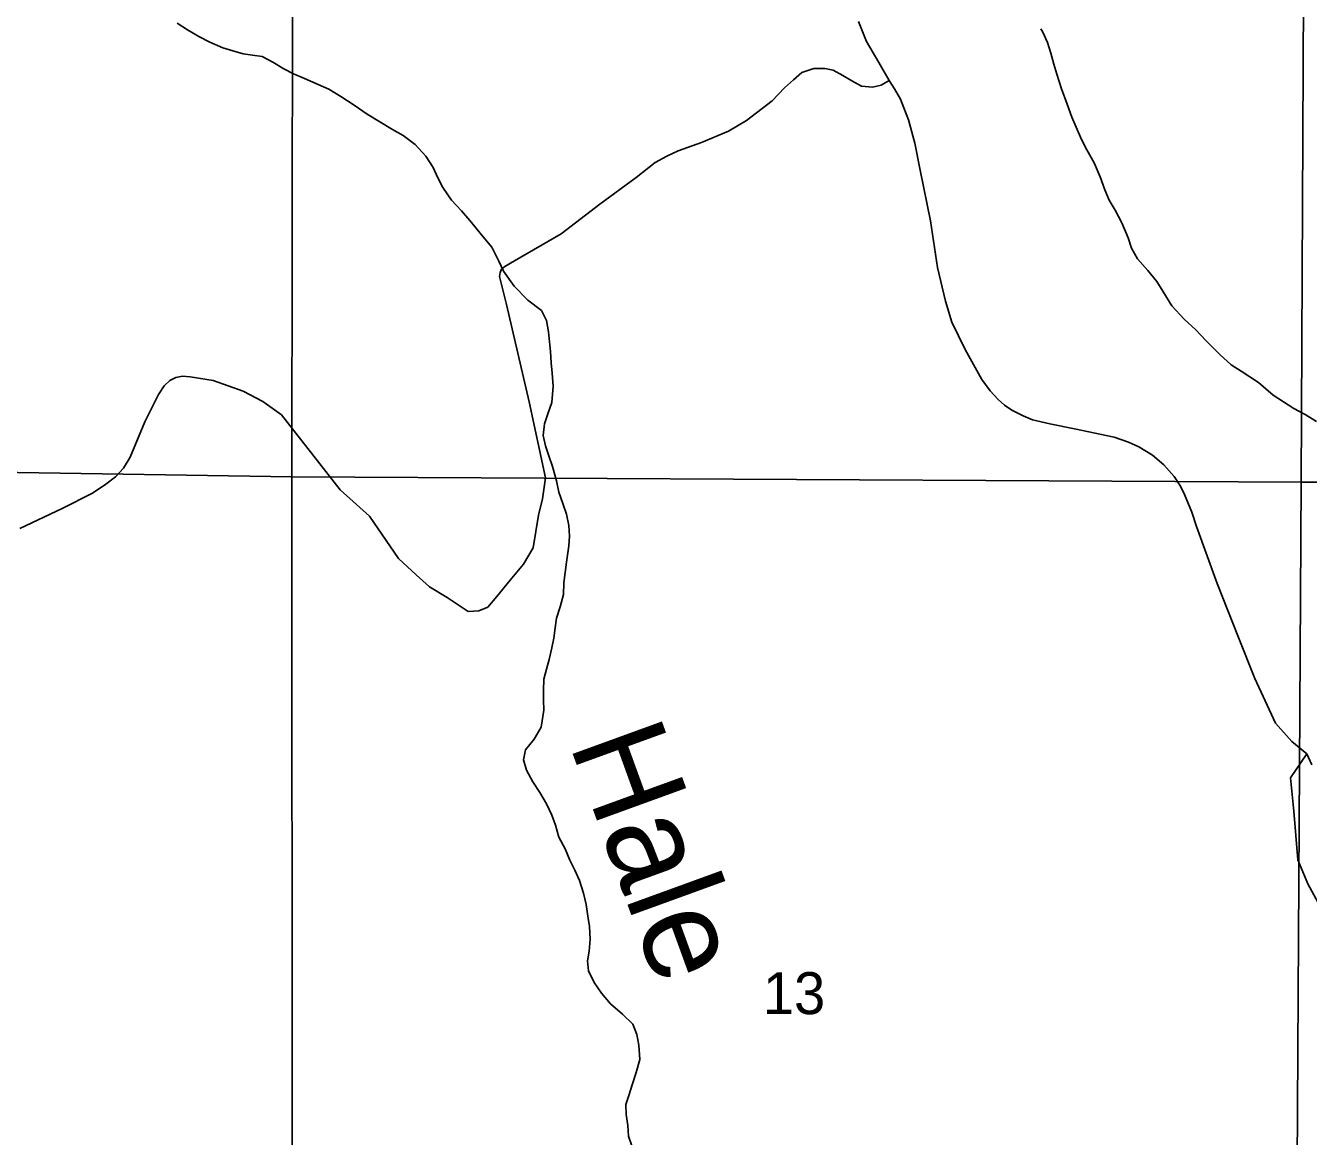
# Model space of a CAD drawing. Extents: x 0 to 34, y 0 to 22.
# Drawn here: x 3.273 to 4.552, y 19.493 to 20.6 of the extents above; entities that cross this region are included whole.
import ezdxf

# ---------------------------------------------------------------- set-up
doc = ezdxf.new("R2010")
doc.units = 0
for name, color, linetype in [('Default', 7, 'Continuous'), ('GM_X_Minor_River', 7, 'Continuous'), ('GM_X_Minor_River_Text', 7, 'Continuous'), ('GM_X_Section', 7, 'Continuous'), ('GM_X_Section_Text', 7, 'Continuous'), ('GM_X_State_Route', 7, 'Continuous'), ('GM_X_Township_Road', 7, 'Continuous')]:
    doc.layers.add(name, color=color, linetype=linetype)

msp = doc.modelspace()

# ---------------------------------------------------------------- linework, layer by layer
at = {"layer": 'Default'}
for p, q in [((3.5394, 20.9), (3.5383, 20.1501)), ((3.5383, 20.1501), (3.5394, 20.9)), ((4.5449, 20.1449), (4.5485, 20.9)), ((4.5485, 20.9), (4.5449, 20.1449)), ((2.5263, 20.1669), (3.5383, 20.1501)), ((3.5383, 20.1501), (4.5449, 20.1449)), ((4.5449, 20.1449), (5.5506, 20.1397))]:
    msp.add_line(p, q, dxfattribs=at)
at = {"layer": 'GM_X_Minor_River'}
for p, q in [((3.4342, 20.5958), (3.4241, 20.6024)), ((3.4458, 20.5893), (3.4342, 20.5958)), ((4.2871, 20.5936), (4.2854, 20.5969)), ((4.292, 20.5831), (4.2871, 20.5936)), ((3.4566, 20.5836), (3.4458, 20.5893)), ((3.4697, 20.5779), (3.4566, 20.5836)), ((4.2953, 20.5725), (4.292, 20.5831)), ((3.4797, 20.5748), (3.4697, 20.5779)), ((3.4897, 20.5721), (3.4797, 20.5748)), ((3.4992, 20.5705), (3.4897, 20.5721)), ((3.5088, 20.5693), (3.4992, 20.5705)), ((3.5196, 20.5635), (3.5088, 20.5693)), ((4.2983, 20.5616), (4.2953, 20.5725)), ((3.5305, 20.557), (3.5196, 20.5635)), ((3.5401, 20.552), (3.5305, 20.557)), ((4.3013, 20.5518), (4.2983, 20.5616)), ((3.5509, 20.5474), (3.5401, 20.552)), ((3.5648, 20.5414), (3.5509, 20.5474)), ((4.3059, 20.5371), (4.3013, 20.5518)), ((3.5752, 20.5367), (3.5648, 20.5414)), ((3.5872, 20.5295), (3.5752, 20.5367)), ((3.6004, 20.5208), (3.5872, 20.5295)), ((4.3114, 20.5217), (4.3059, 20.5371)), ((3.6136, 20.5117), (3.6004, 20.5208)), ((4.3163, 20.5089), (4.3114, 20.5217)), ((3.626, 20.5041), (3.6136, 20.5117)), ((3.6388, 20.4965), (3.626, 20.5041)), ((4.3205, 20.4988), (4.3163, 20.5089)), ((3.6493, 20.4904), (3.6388, 20.4965)), ((4.3258, 20.4864), (4.3205, 20.4988)), ((3.6613, 20.4816), (3.6493, 20.4904)), ((3.672, 20.4698), (3.6613, 20.4816)), ((4.331, 20.4763), (4.3258, 20.4864)), ((3.6792, 20.4586), (3.672, 20.4698)), ((4.3383, 20.4632), (4.331, 20.4763)), ((3.6836, 20.4489), (3.6792, 20.4586)), ((4.3444, 20.4494), (4.3383, 20.4632)), ((3.6889, 20.4388), (3.6836, 20.4489)), ((4.349, 20.4362), (4.3444, 20.4494)), ((3.6977, 20.4261), (3.6889, 20.4388)), ((4.3535, 20.4261), (4.349, 20.4362)), ((3.7075, 20.4154), (3.6977, 20.4261)), ((3.7158, 20.4058), (3.7075, 20.4154)), ((4.3595, 20.416), (4.3535, 20.4261)), ((4.366, 20.4033), (4.3595, 20.416)), ((3.7292, 20.3895), (3.7158, 20.4058)), ((4.3722, 20.3886), (4.366, 20.4033)), ((3.7379, 20.3791), (3.7292, 20.3895)), ((4.3756, 20.3781), (4.3722, 20.3886)), ((3.7448, 20.3652), (3.7379, 20.3791)), ((4.3816, 20.3676), (4.3756, 20.3781)), ((3.7493, 20.3551), (3.7448, 20.3652)), ((4.3919, 20.3558), (4.3816, 20.3676)), ((3.7601, 20.3402), (3.7493, 20.3551)), ((4.4009, 20.3451), (4.3919, 20.3558)), ((3.7738, 20.3262), (3.7601, 20.3402)), ((4.4069, 20.3354), (4.4009, 20.3451)), ((3.7874, 20.316), (3.7738, 20.3262)), ((4.4158, 20.3208), (4.4069, 20.3354)), ((3.7923, 20.3062), (3.7874, 20.316)), ((4.4283, 20.3075), (4.4158, 20.3208)), ((3.7942, 20.2949), (3.7923, 20.3062)), ((4.4397, 20.2968), (4.4283, 20.3075)), ((3.7953, 20.2847), (3.7942, 20.2949)), ((4.4503, 20.2858), (4.4397, 20.2968)), ((3.7963, 20.2752), (3.7953, 20.2847)), ((3.797, 20.2638), (3.7963, 20.2752)), ((4.4637, 20.2721), (4.4503, 20.2858)), ((3.7981, 20.2536), (3.797, 20.2638)), ((4.475, 20.2618), (4.4637, 20.2721)), ((4.4851, 20.2557), (4.475, 20.2618)), ((3.7989, 20.2407), (3.7981, 20.2536)), ((4.5022, 20.2444), (4.4851, 20.2557)), ((3.7975, 20.2243), (3.7989, 20.2407)), ((4.517, 20.2316), (4.5022, 20.2444)), ((3.7937, 20.2131), (3.7975, 20.2243)), ((4.5271, 20.225), (4.517, 20.2316)), ((4.5376, 20.2182), (4.5271, 20.225)), ((3.7902, 20.2031), (3.7937, 20.2131)), ((4.5488, 20.2124), (4.5376, 20.2182)), ((4.5601, 20.2052), (4.5488, 20.2124)), ((3.7891, 20.1913), (3.7902, 20.2031)), ((3.7913, 20.1811), (3.7891, 20.1913)), ((3.7946, 20.171), (3.7913, 20.1811)), ((3.7984, 20.1604), (3.7946, 20.171)), ((3.8023, 20.1461), (3.7984, 20.1604)), ((3.8045, 20.1348), (3.8023, 20.1461)), ((3.8087, 20.1235), (3.8045, 20.1348)), ((3.8124, 20.113), (3.8087, 20.1235)), ((3.8147, 20.1016), (3.8124, 20.113)), ((3.8154, 20.091), (3.8147, 20.1016)), ((3.8124, 20.065), (3.8145, 20.0815)), ((3.8145, 20.0815), (3.8154, 20.091)), ((3.8108, 20.0547), (3.8124, 20.065)), ((3.8092, 20.033), (3.8096, 20.0444)), ((3.8096, 20.0444), (3.8108, 20.0547)), ((3.8058, 20.0204), (3.8092, 20.033)), ((3.8024, 20.0092), (3.8058, 20.0204)), ((3.8011, 19.9997), (3.8024, 20.0092)), ((3.7996, 19.9894), (3.8011, 19.9997)), ((3.7949, 19.9679), (3.7976, 19.9798)), ((3.7976, 19.9798), (3.7996, 19.9894)), ((3.7922, 19.9583), (3.7949, 19.9679)), ((3.7898, 19.9484), (3.7922, 19.9583)), ((3.7894, 19.9373), (3.7898, 19.9484)), ((3.7893, 19.9274), (3.7894, 19.9373)), ((3.7871, 19.9004), (3.7896, 19.9176)), ((3.7896, 19.9176), (3.7893, 19.9274)), ((3.7799, 19.8887), (3.7871, 19.9004)), ((3.7695, 19.8679), (3.7715, 19.8778)), ((3.7715, 19.8778), (3.7799, 19.8887)), ((3.7725, 19.8577), (3.7695, 19.8679)), ((3.7786, 19.8461), (3.7725, 19.8577)), ((3.7858, 19.8353), (3.7786, 19.8461)), ((3.7922, 19.8241), (3.7858, 19.8353)), ((3.7975, 19.8129), (3.7922, 19.8241)), ((3.8012, 19.8027), (3.7975, 19.8129)), ((3.8046, 19.791), (3.8012, 19.8027)), ((3.8111, 19.7791), (3.8046, 19.791)), ((3.8156, 19.7678), (3.8111, 19.7791)), ((3.8205, 19.7581), (3.8156, 19.7678)), ((3.8254, 19.7476), (3.8205, 19.7581)), ((3.8292, 19.7351), (3.8254, 19.7476)), ((3.8318, 19.7238), (3.8292, 19.7351)), ((3.8337, 19.7121), (3.8318, 19.7238)), ((3.8352, 19.7019), (3.8337, 19.7121)), ((3.836, 19.6893), (3.8352, 19.7019)), ((3.8348, 19.6771), (3.836, 19.6893)), ((3.8332, 19.6676), (3.8348, 19.6771)), ((3.8343, 19.6577), (3.8332, 19.6676)), ((3.84, 19.6461), (3.8343, 19.6577)), ((3.8471, 19.6353), (3.84, 19.6461)), ((3.8562, 19.6246), (3.8471, 19.6353)), ((3.868, 19.6143), (3.8562, 19.6246)), ((3.8785, 19.6043), (3.868, 19.6143)), ((3.8823, 19.5942), (3.8785, 19.6043)), ((3.8845, 19.5836), (3.8823, 19.5942)), ((3.8853, 19.5692), (3.8845, 19.5836)), ((3.8816, 19.5561), (3.8853, 19.5692)), ((3.8778, 19.5439), (3.8816, 19.5561)), ((3.8715, 19.5243), (3.8746, 19.5343)), ((3.8746, 19.5343), (3.8778, 19.5439)), ((3.8718, 19.5144), (3.8715, 19.5243)), ((3.8733, 19.5034), (3.8718, 19.5144)), ((3.874, 19.4928), (3.8733, 19.5034)), ((3.8774, 19.483), (3.874, 19.4928))]:
    msp.add_line(p, q, dxfattribs=at)
at = {"layer": 'GM_X_Section'}
for p, q in [((2.5263, 20.1669), (3.5383, 20.1501)), ((3.5383, 20.1501), (3.5387, 19.1524)), ((3.5387, 19.1524), (3.5383, 20.1501)), ((3.5383, 20.1501), (4.5449, 20.1449)), ((4.5449, 20.1449), (4.5388, 19.1444)), ((4.5388, 19.1444), (4.5449, 20.1449)), ((4.5449, 20.1449), (5.5506, 20.1397))]:
    msp.add_line(p, q, dxfattribs=at)
at = {"layer": 'GM_X_State_Route'}
for p, q in [((4.1113, 20.5844), (4.1034, 20.6043)), ((4.1236, 20.5634), (4.1113, 20.5844)), ((4.1339, 20.5455), (4.1236, 20.5634)), ((4.1395, 20.5372), (4.1339, 20.5455)), ((4.1454, 20.5269), (4.1395, 20.5372)), ((4.1486, 20.5181), (4.1454, 20.5269)), ((4.1534, 20.5062), (4.1486, 20.5181)), ((4.1597, 20.4828), (4.1534, 20.5062)), ((4.1649, 20.4558), (4.1597, 20.4828)), ((4.1752, 20.4055), (4.1649, 20.4558)), ((4.1823, 20.359), (4.1752, 20.4055)), ((4.1903, 20.3252), (4.1823, 20.359)), ((4.1966, 20.3044), (4.1903, 20.3252)), ((4.2099, 20.2771), (4.1966, 20.3044)), ((4.2181, 20.2622), (4.2099, 20.2771)), ((4.2264, 20.2472), (4.2181, 20.2622)), ((4.2347, 20.236), (4.2264, 20.2472)), ((4.2426, 20.2274), (4.2347, 20.236)), ((4.2489, 20.2218), (4.2426, 20.2274)), ((4.2563, 20.2167), (4.2489, 20.2218)), ((4.2676, 20.211), (4.2563, 20.2167)), ((4.277, 20.2071), (4.2676, 20.211)), ((4.2943, 20.2029), (4.277, 20.2071)), ((4.3187, 20.1979), (4.2943, 20.2029)), ((4.3583, 20.1896), (4.3187, 20.1979)), ((4.3728, 20.1848), (4.3583, 20.1896)), ((4.3831, 20.1801), (4.3728, 20.1848)), ((4.3965, 20.1717), (4.3831, 20.1801)), ((4.4079, 20.1621), (4.3965, 20.1717)), ((4.4181, 20.1505), (4.4079, 20.1621)), ((4.4245, 20.141), (4.4181, 20.1505)), ((4.4284, 20.1327), (4.4245, 20.141)), ((4.4358, 20.115), (4.4284, 20.1327)), ((4.4405, 20.1008), (4.4358, 20.115)), ((4.4611, 20.0437), (4.4405, 20.1008)), ((4.4823, 19.9901), (4.4611, 20.0437)), ((4.4987, 19.9491), (4.4823, 19.9901)), ((4.5194, 19.9047), (4.4987, 19.9491)), ((4.5357, 19.8864), (4.5194, 19.9047)), ((4.5505, 19.8741), (4.5357, 19.8864)), ((4.5554, 19.8631), (4.5505, 19.8741))]:
    msp.add_line(p, q, dxfattribs=at)
at = {"layer": 'GM_X_Township_Road'}
for p, q in [((4.0469, 20.5532), (4.0588, 20.5573)), ((4.0588, 20.5573), (4.07, 20.5572)), ((4.07, 20.5572), (4.0782, 20.5558)), ((4.0782, 20.5558), (4.0879, 20.5503)), ((4.0296, 20.5379), (4.0385, 20.546)), ((4.0385, 20.546), (4.0469, 20.5532)), ((4.0879, 20.5503), (4.0969, 20.5451)), ((4.0969, 20.5451), (4.1066, 20.5398)), ((4.126, 20.5408), (4.1339, 20.5455)), ((4.0175, 20.5252), (4.0296, 20.5379)), ((4.1066, 20.5398), (4.1174, 20.5387)), ((4.1174, 20.5387), (4.126, 20.5408)), ((3.9919, 20.5054), (4.0175, 20.5252)), ((3.9737, 20.4949), (3.9919, 20.5054)), ((3.9469, 20.4837), (3.9737, 20.4949)), ((3.9235, 20.4753), (3.9469, 20.4837)), ((3.9007, 20.4636), (3.9122, 20.47)), ((3.9122, 20.47), (3.9235, 20.4753)), ((3.8817, 20.4487), (3.9007, 20.4636)), ((3.8454, 20.4222), (3.8817, 20.4487)), ((3.807, 20.3924), (3.8454, 20.4222)), ((3.7604, 20.3656), (3.807, 20.3924)), ((3.7509, 20.3599), (3.7604, 20.3656)), ((3.7456, 20.3499), (3.746, 20.354)), ((3.746, 20.354), (3.7475, 20.3571)), ((3.7475, 20.3571), (3.7509, 20.3599)), ((3.7526, 20.3219), (3.7456, 20.3499)), ((3.7751, 20.225), (3.7526, 20.3219)), ((3.4168, 20.2462), (3.4226, 20.2493)), ((3.4226, 20.2493), (3.4295, 20.2505)), ((3.4295, 20.2505), (3.4371, 20.2498)), ((3.4371, 20.2498), (3.4599, 20.2462)), ((3.4054, 20.2322), (3.4112, 20.2409)), ((3.4112, 20.2409), (3.4168, 20.2462)), ((3.4599, 20.2462), (3.4899, 20.2355)), ((3.4899, 20.2355), (3.5094, 20.2253)), ((3.3919, 20.205), (3.4054, 20.2322)), ((3.5094, 20.2253), (3.528, 20.212)), ((3.7913, 20.1491), (3.7751, 20.225)), ((3.528, 20.212), (3.5866, 20.1372)), ((3.3772, 20.1698), (3.3919, 20.205)), ((3.3625, 20.1502), (3.3706, 20.1587)), ((3.3706, 20.1587), (3.3772, 20.1698)), ((3.3529, 20.1427), (3.3625, 20.1502)), ((3.7882, 20.1284), (3.7913, 20.1491)), ((3.3094, 20.1187), (3.3395, 20.134)), ((3.3395, 20.134), (3.3529, 20.1427)), ((3.5866, 20.1372), (3.6157, 20.1109)), ((3.7844, 20.1121), (3.7882, 20.1284)), ((3.267, 20.0985), (3.3094, 20.1187)), ((3.6157, 20.1109), (3.6448, 20.0687)), ((3.7789, 20.0795), (3.7844, 20.1121)), ((3.6448, 20.0687), (3.6623, 20.0523)), ((3.7693, 20.063), (3.7789, 20.0795)), ((3.756, 20.0471), (3.7693, 20.063)), ((3.6623, 20.0523), (3.6756, 20.0404)), ((3.7427, 20.0309), (3.756, 20.0471)), ((3.6756, 20.0404), (3.6932, 20.03)), ((3.7337, 20.0202), (3.7427, 20.0309)), ((3.6932, 20.03), (3.7142, 20.0159)), ((3.7247, 20.0166), (3.7337, 20.0202)), ((3.7142, 20.0159), (3.7247, 20.0166)), ((4.5343, 19.85), (4.5505, 19.8741)), ((4.5377, 19.8167), (4.5343, 19.85)), ((4.5414, 19.7683), (4.5377, 19.8167)), ((4.5515, 19.7444), (4.5414, 19.7683)), ((4.5655, 19.7188), (4.5515, 19.7444))]:
    msp.add_line(p, q, dxfattribs=at)

# ---------------------------------------------------------------- texts
at = {"layer": 'GM_X_Minor_River_Text'}
msp.add_text('Hale', height=0.09469, rotation=289.9705, dxfattribs=at).set_placement((3.8149, 19.8837))
at = {"layer": 'GM_X_Section_Text'}
msp.add_text('13', height=0.04186, rotation=0, dxfattribs=at).set_placement((4.008, 19.6144))

doc.saveas('drawing.dxf')
